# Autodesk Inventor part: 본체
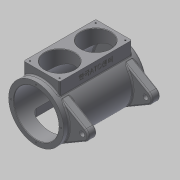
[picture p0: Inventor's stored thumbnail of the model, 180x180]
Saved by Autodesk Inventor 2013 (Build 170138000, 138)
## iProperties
Created: 2016-11
Part Number: 본체
Material: 일반
Document SubType Name: Modeling
Designer: mduedu
Density: 1 g/cm^3
Author: mduedu
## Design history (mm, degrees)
sketch "스케치1"
  geometry: C1 r 65 at (0, 0); 1 further point
  constraints: 1 centre point, 1 coincident
  dimensions: "d119" = 130 diameter of C1
extrude "돌출1" new body sketch "스케치1" distance "d3" = 98; taper "d4" = 0 deg; dims "d132" = 97, "d133" = 0
feature "쉘1" dims "d120" = 12, "d134" = 8
node "작업 평면2"
sketch "스케치13"
  geometry: L1 (42.5, 85)-(-42.5, 85); L2 (-42.5, 85)-(-42.5, -85); L3 (-42.5, -85)-(42.5, -85); L4 (42.5, -85)-(42.5, 85); 2 further points
  constraints: 8 end point, 2 parallel, 1 horizontal, 1 midpoint, 1 perpendicular, 1 vertical alignment
  dimensions: "d122" = 170 distance of L1.end L2.end; "d124" = 85 distance of L2.end L3.end; "d125" = 85 distance from line of point (0, 0) L1 (= 0.5 x d122)
extrude "돌출11" join sketch "스케치13" stored distance "d126" = 10; taper "d127" = 0 deg
sketch "스케치14"
  geometry: L1 (65, 97)-(-65, 97) reference; C1 r 35 at (0, 42.5); 1 further point
  constraints: 1 centre point, 1 vertical alignment
  dimensions: "d128" = 70 diameter of C1; "d129" = 54.5 distance from line of C1.centre L1
extrude "돌출12" cut sketch "스케치14" stored distance "d130" = 10; taper "d131" = 0 deg
sketch "스케치15"
  geometry: C1 r 53 at (0, 0) reference; 1 further point
extrude "돌출13" cut sketch "스케치15" stored distance "d135" = 10; taper "d136" = 0 deg
chamfer "모따기1" distance "d54" = 1; stored, may be unused: second distance "d55" = 2, angle "d56" = 45 deg
sketch "스케치8"
  geometry: C1 r 23 at (0, 0); C2 r 65 at (0, 0) reference; 1 further point
  constraints: 1 centre point, 1 concentric
  dimensions: "d57" = 46 diameter of C1
extrude "돌출8" join sketch "스케치8" distance "d58" = 14; taper "d59" = 0 deg
feature "면 기울기1" dims angle "d202" = 10 deg
hole "구멍3" diameter "d62" = 24; stored, may be unused: countersink angle "d66" = 90 deg, drill point angle "d68" = 0 deg; dims "d63" = 6, "d64" = 28, "d65" = 8, "d67" = 14, "d169" = 10, "d170" = 10
fillet "모깎기11" dims "d69" = 3
fillet "모깎기12" dims "d70" = 3
fillet "모깎기13" dims "d71" = 0.3
chamfer "모따기2" distance "d72" = 1; stored, may be unused: second distance "d73" = 2, angle "d74" = 45 deg
node "작업 평면3"
sketch "스케치16"
  geometry: L1 (-42.5, -80)-(52.5, -80); L2 (-42.5, -80)-(24.675, -12.825); L3 (-42.5, -80)-(24.675, -147.175); L4 (3.462, -34.038)-(60.057, -67.042); L5 (3.462, -125.962)-(60.057, -92.958); A1 r 65 centre (-42.5, -80) between (3.462, -34.038) and (3.462, -125.962) reference; A2 r 65 centre (-42.5, -80) between (3.462, -125.962) and (3.462, -34.038); A3 r 95 centre (-42.5, -80) between (52.5, -80) and (24.675, -147.175); A4 r 15 centre (52.5, -80) between (60.057, -67.042) and (60.057, -92.958); 1 further point
  constraints: 10 end point, 9 point on circle, 3 centre point, 3 coincident, 2 point on line, 2 tangent, 1 horizontal
  dimensions: "d140" = 45 deg angle of L3 L1; "d141" = 45 deg angle of L2 L1; "d194" = 30 radial gap between concentric circles of A3 A1; "d195" = 30 diameter of A4
extrude "돌출14" join sketch "스케치16" distance "d143" = 20; taper "d144" = 0 deg
fillet "모깎기25" dims "d196" = 3
fillet "모깎기26" dims "d197" = 3
sketch "스케치22"
  geometry: C1 r 6 at (52.5, -80); A1 r 15 centre (52.5, -80) between (60.057, -92.958) and (60.057, -67.042) reference; 1 further point
  constraints: 1 centre point, 1 coincident
  dimensions: "d198" = 12 diameter of C1
extrude "돌출17" cut sketch "스케치22" stored distance "d200" = 10; taper "d201" = 0 deg
fillet "모깎기20" dims "d159" = 3
fillet "모깎기21" dims "d160" = 3
fillet "모깎기22" dims "d161" = 3
node "작업 평면4"
sketch "스케치18"
  geometry: L1 (-42.5, 65)-(42.5, 65); L2 (42.5, 65)-(42.5, -65); L3 (42.5, -65)-(-42.5, -65); L4 (-42.5, -65)-(-42.5, 65); 2 further points
  constraints: 8 end point, 2 parallel, 1 horizontal, 1 midpoint, 1 perpendicular, 1 vertical alignment
  dimensions: "d162" = 130 distance of L1.end L2.end; "d164" = 85 distance of L2.end L3.end; "d165" = 65 distance from line of point (0, 0) L1 (= 0.5 x d162)
extrude "돌출16" cut sketch "스케치18" stored distance "d166" = 15; taper "d167" = 0 deg
fillet "모깎기23" dims "d168" = 10
fillet "모깎기24" dims "d173" = 3
sketch "스케치19"
  geometry: 4 further points
  constraints: 4 other
hole "구멍6" sketch "스케치19" at (0, -59), (59, 0), (-59, 0), (0, 59) diameter "d174" = 3.242; stored, may be unused: countersink angle "d178" = 90 deg, drill point angle "d180" = 120 deg; dims "d175" = 7, "d176" = 4, "d177" = 2, "d179" = 9
sketch "스케치20"
  geometry: L1 (35, -77.5)-(-35, -77.5); L2 (-35, -77.5)-(-35, -7.5); L3 (-35, -7.5)-(35, -7.5); L4 (35, -7.5)-(35, -77.5); L5 (35, -77.5)-(-35, -7.5); L6 (-35, -77.5)-(35, -7.5); C1 r 36 at (0, -42.5) reference; 3 further points
  constraints: 12 end point, 2 coincident, 2 midpoint, 2 parallel, 1 horizontal, 1 perpendicular
  dimensions: "d181" = 70 distance of L2.end L3.end; "d182" = 70 distance of L1.end L2.end
hole "구멍7" sketch "스케치20" at (-35, -77.5), (35, -77.5) diameter "d183" = 3.242; stored, may be unused: countersink angle "d187" = 90 deg, drill point angle "d189" = 118 deg; dims "d184" = 7, "d185" = 4, "d186" = 2, "d188" = 9
sketch "스케치21"
  geometry: L1 (164, 0)-(0, 0) reference; L2 (-3, 0)-(-3, -24.649) reference; 3 further points
  constraints: 1 midpoint, 1 vertical alignment, 1 other
  dimensions: "d190" = 15 distance from line of point (82, -15) L1; "d191" = 85 distance from line of point (82, 0) L2 (derived)
feature "엠보싱2" sketch "스케치21" dims "d119" = 130, "d192" = 0.5, "d193" = 0
node "솔리드1"
mirror "대칭5"
mirror "대칭6"
mirror "대칭7"
